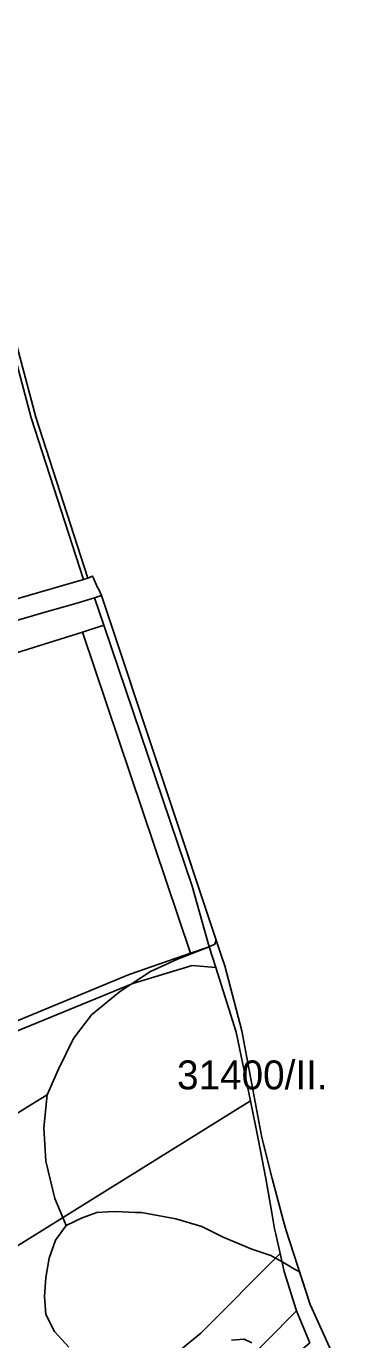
# Model space of a CAD drawing. Extents: x -522079 to -518792, y -1142400 to -1139961.
# Drawn here: x -520002 to -519834, y -1140651 to -1139970 of the extents above; entities that cross this region are included whole.
import ezdxf

# ---------------------------------------------------------------- set-up
doc = ezdxf.new("R2010")
doc.units = 0
for name, color, linetype in [('Hranice parcel', 7, 'Continuous'), ('Parcelní čísla', 7, 'Continuous'), ('Poz předměty', 7, 'Continuous'), ('Značky bodu BP', 7, 'Continuous')]:
    doc.layers.add(name, color=color, linetype=linetype)

msp = doc.modelspace()

# ---------------------------------------------------------------- linework, layer by layer
at = {"layer": 'Hranice parcel'}
msp.add_lwpolyline([(-520044.21, -1139976.9), (-520040.68, -1139992.3), (-520017.23, -1140098.3), (-519997.42, -1140172.65), (-519970.54, -1140256.24), (-519972.75, -1140256.9), (-519999.86, -1140173.01), (-520019.48, -1140099.15), (-520042.94, -1139993.02), (-520047.4, -1139971.94), (-520045.81, -1139969.91)], close=True, dxfattribs=at)
for points in [[(-520039.59, -1140276.29), (-519972.75, -1140256.9), (-519970.54, -1140256.24), (-519967.99, -1140255.12), (-519967.34, -1140256.59), (-519967.14, -1140257.04), (-519965.23, -1140261.32), (-519965.02, -1140261.78), (-519963.47, -1140265.25), (-519967, -1140266.42), (-519976.66, -1140269.42), (-519993.22, -1140274.03), (-520037.05, -1140286.83)], [(-519855.49, -1140652.85), (-519862.3, -1140636.3), (-519868.76, -1140615.85), (-519870.83, -1140606.54), (-519873.07, -1140596.47), (-519873.69, -1140593.69), (-519875.11, -1140585.42), (-519878.23, -1140567.62), (-519882.2, -1140547.1), (-519886.24, -1140527.38), (-519893.54, -1140491.71), (-519904.17, -1140458.14), (-519907.62, -1140447.38), (-519916.36, -1140415.97), (-519962.19, -1140280.64), (-519967, -1140266.42), (-519963.47, -1140265.25), (-519901.13, -1140452.27), (-519899.47, -1140457.37), (-519890.68, -1140491.02), (-519880.22, -1140546.4), (-519874.89, -1140567.55), (-519868.98, -1140589.75), (-519867.83, -1140594.09), (-519855.18, -1140633.03), (-519833.7, -1140680.7)], [(-520031.39, -1140495.83), (-519949.02, -1140461.79), (-519917.2, -1140450.72), (-519907.62, -1140447.38), (-519904.17, -1140458.14), (-519916.36, -1140457.2), (-519947.24, -1140466.47), (-520104.66, -1140531.14)]]:
    msp.add_lwpolyline(points, dxfattribs=at)
at = {"layer": 'Parcelní čísla'}
for points in [[(-520178.95, -1140054.65), (-520121.19, -1140041.17), (-520101.17, -1140033.45), (-520091.68, -1140028.41), (-520082.48, -1140019.36), (-520062.19, -1139990.92), (-520047.4, -1139971.94), (-520042.94, -1139993.02), (-520019.48, -1140099.15), (-519999.86, -1140173.01), (-519972.75, -1140256.9), (-520039.59, -1140276.29), (-520091.03, -1140291.29)], [(-519973.33, -1140284.13), (-519962.19, -1140280.64), (-519916.36, -1140415.97), (-519907.62, -1140447.38), (-519917.2, -1140450.72)], [(-520087.13, -1140319.85), (-519973.33, -1140284.13), (-519917.2, -1140450.72), (-519949.02, -1140461.79), (-520031.39, -1140495.83), (-520041.44, -1140499.76)], [(-519886.24, -1140527.38), (-520082.56, -1140649.64), (-520126.03, -1140587.59), (-520155.91, -1140552.2), (-520104.66, -1140531.14), (-519947.24, -1140466.47), (-519916.36, -1140457.2), (-519904.17, -1140458.14), (-519893.54, -1140491.71)], [(-519911.88, -1140647.84), (-520013.2, -1140730.8), (-520072.01, -1140664.71), (-520082.56, -1140649.64), (-519886.24, -1140527.38), (-519882.2, -1140547.1), (-519878.23, -1140567.62), (-519875.11, -1140585.42), (-519873.69, -1140593.69), (-519873.07, -1140596.47), (-519870.83, -1140606.54)], [(-519862.3, -1140636.3), (-519855.49, -1140652.85), (-519981.63, -1140760.4), (-519991.87, -1140748.27), (-519893.23, -1140667.47)]]:
    msp.add_lwpolyline(points, close=True, dxfattribs=at)
at = {"layer": 'Poz předměty'}
msp.add_lwpolyline([(-520037.05, -1140286.83), (-519993.22, -1140274.03), (-519976.66, -1140269.42), (-519967, -1140266.42), (-519962.19, -1140280.64), (-519973.33, -1140284.13), (-520087.13, -1140319.85)], dxfattribs=at)
msp.add_lwpolyline([(-519862.3, -1140636.3), (-519893.23, -1140667.47), (-519991.87, -1140748.27), (-520001.24, -1140755.77), (-520010.06, -1140762.16), (-520068.52, -1140802.68), (-520119.77, -1140834.99), (-520149.6, -1140820.02), (-520083.41, -1140780.15), (-520025.44, -1140739.97), (-520022.9, -1140738.15), (-520013.2, -1140730.8), (-519911.88, -1140647.84), (-519870.83, -1140606.54), (-519868.76, -1140615.85)], close=True, dxfattribs=at)
at = {"layer": 'Značky bodu BP'}
for points in [[(-520017.23, -1140098.3), (-519997.42, -1140172.65), (-519970.54, -1140256.24), (-519967.99, -1140255.12), (-519967.34, -1140256.59), (-519967.14, -1140257.04), (-519965.23, -1140261.32), (-519965.02, -1140261.78), (-519963.47, -1140265.25), (-519903.91, -1140443.93), (-519904.58, -1140446.1), (-519906.87, -1140447.15), (-519907.6, -1140447.43), (-519923.94, -1140453.82), (-519938, -1140460.16), (-519948.06, -1140466.81), (-519949.47, -1140467.74), (-519954.25, -1140470.9), (-519968.66, -1140482.76), (-519977.89, -1140494.99), (-519985.65, -1140510.92), (-519991.56, -1140524.26), (-520000, -1140529.44), (-520009.66, -1140535.38)], [(-520009.66, -1140535.38), (-520000, -1140529.44), (-519991.56, -1140524.26), (-519993.3, -1140541.36), (-519992.31, -1140558.59), (-519987.57, -1140578.01), (-519983.42, -1140587.9), (-519981.74, -1140591.91), (-519987.24, -1140599.63), (-519990.53, -1140609), (-519992.18, -1140618.93), (-519993.01, -1140628.85), (-519992.18, -1140638.23), (-519987.78, -1140647.05), (-519980.36, -1140655.04)], [(-519980.36, -1140655.04), (-519987.78, -1140647.05), (-519992.18, -1140638.23), (-519993.01, -1140628.85), (-519992.18, -1140618.93), (-519990.53, -1140609), (-519987.24, -1140599.63), (-519981.74, -1140591.91), (-519973.49, -1140588.05), (-519965.8, -1140585.29), (-519960.2, -1140584.98), (-519955.91, -1140584.75), (-519945.77, -1140585.17), (-519942.72, -1140585.29), (-519924.85, -1140588.6), (-519911.39, -1140592.46), (-519900.39, -1140597.98), (-519885.55, -1140604.32), (-519875.66, -1140607.62), (-519873.22, -1140608.94), (-519869.89, -1140610.74), (-519869.42, -1140611), (-519868.52, -1140611.49), (-519865.59, -1140613.3), (-519864.64, -1140613.89), (-519860.68, -1140616.1), (-519855.18, -1140633.03), (-519839.36, -1140668.14)], [(-519896, -1140651.46), (-519889.4, -1140650.91), (-519885.55, -1140652.84)], [(-519885.55, -1140652.84), (-519889.4, -1140650.91), (-519896, -1140651.46)]]:
    msp.add_lwpolyline(points, dxfattribs=at)
msp.add_lwpolyline([(-519855.18, -1140633.03), (-519860.68, -1140616.1), (-519864.64, -1140613.89), (-519865.59, -1140613.3), (-519868.52, -1140611.49), (-519869.42, -1140611), (-519869.89, -1140610.74), (-519873.22, -1140608.94), (-519875.66, -1140607.62), (-519885.55, -1140604.32), (-519900.39, -1140597.98), (-519911.39, -1140592.46), (-519924.85, -1140588.6), (-519942.72, -1140585.29), (-519945.77, -1140585.17), (-519955.91, -1140584.75), (-519960.2, -1140584.98), (-519965.8, -1140585.29), (-519973.49, -1140588.05), (-519981.74, -1140591.91), (-519983.42, -1140587.9), (-519987.57, -1140578.01), (-519992.31, -1140558.59), (-519993.3, -1140541.36), (-519991.56, -1140524.26), (-519985.65, -1140510.92), (-519977.89, -1140494.99), (-519968.66, -1140482.76), (-519954.25, -1140470.9), (-519949.47, -1140467.74), (-519948.06, -1140466.81), (-519938, -1140460.16), (-519923.94, -1140453.82), (-519907.6, -1140447.43), (-519906.87, -1140447.15), (-519904.58, -1140446.1), (-519903.91, -1140443.93), (-519901.13, -1140452.27), (-519899.47, -1140457.37), (-519890.68, -1140491.02), (-519880.22, -1140546.4), (-519874.89, -1140567.55), (-519868.98, -1140589.75), (-519867.83, -1140594.09)], close=True, dxfattribs=at)

# ---------------------------------------------------------------- texts
msp.add_text('31400/II.', height=15, rotation=0, dxfattribs=at).set_placement((-519924.24, -1140521.37))

doc.saveas('drawing.dxf')
